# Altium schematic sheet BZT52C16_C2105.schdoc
size 127 x 101 mm
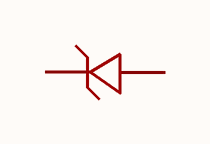
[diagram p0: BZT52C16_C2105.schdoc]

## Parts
ZD?  bzt52c16_c2105  [SOD-123_L2.8-W1.8-LS3.7-RD]  (value not drawn)

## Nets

Not connected (* = marked no-connect by the designer): ZD? 1(K) 2(A)

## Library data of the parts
ZD? = bzt52c16_c2105: 二极管配置:1个独立式;稳压值(标称值):16V;稳压值(范围):15.3V~17.1V;耗散功率(Pd):500mW;; Manufacturer: CJ(江苏长电/长晶); AddInBom: yes; ModelId: 7884390a25fb4c08947731ebfba7e3f8; ModelTransform: 144.8816,62.992,0,0,0,0,0,0,0; Diode Configuration: 1个独立式; Zener Voltage(Nom): 16V; Reverse Leakage Current (Ir): 100nA@11.2V; Pd - Power Dissipation: 500mW; Impedance(Zzt): 40Ω; Impedance(Zzk): 200Ω; Operating Junction Temperature Range: -55℃~+150℃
